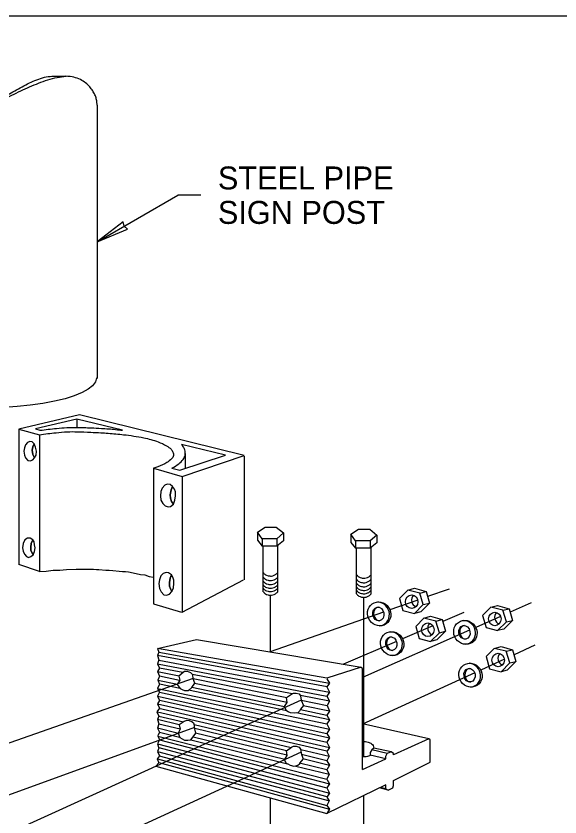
# Model space of a CAD drawing. Extents: x 99862 to 103151, y 103000 to 105076.
# Drawn here: x 102078 to 102457, y 104517 to 105076 of the extents above; entities that cross this region are included whole.
import ezdxf

# ---------------------------------------------------------------- set-up
doc = ezdxf.new("R2010")
doc.units = 0
for name, color, linetype in [('Level 1', 7, 'Continuous'), ('Level 15', 7, 'Continuous'), ('Level 2', 7, 'Continuous'), ('Level 20', 7, 'Continuous'), ('Level 3', 7, 'Continuous')]:
    doc.layers.add(name, color=color, linetype=linetype)

msp = doc.modelspace()

# ---------------------------------------------------------------- linework, layer by layer
at = {"layer": 'Level 1'}
msp.add_lwpolyline([(99862, 102999.5), (103151, 102999.5), (103151, 105075.5), (99862, 105075.5)], close=True, dxfattribs=at)
for points in [[(102194.17, 104618.02), (102191.13, 104615.31), (102191.81, 104612.61), (102190.12, 104609.56), (102192.15, 104606.86), (102193.49, 104606.18), (102195.18, 104605.51), (102197.88, 104605.51), (102200.24, 104607.53), (102202.26, 104610.58), (102201.25, 104613.62), (102200.91, 104616.33), (102199.56, 104617.68), (102197.2, 104618.69), (102195.18, 104618.69), (102194.17, 104618.02)], [(102266.33, 104600.43), (102269.71, 104602.8), (102271.05, 104603.48), (102273.08, 104603.48), (102275.1, 104603.14), (102276.11, 104601.79), (102276.45, 104598.74), (102278.14, 104595.02), (102276.11, 104592.32), (102275.44, 104590.96), (102274.09, 104589.95), (102271.73, 104589.61), (102269.03, 104589.95), (102267.34, 104590.63), (102266.33, 104591.3), (102264.98, 104594.35), (102266.67, 104597.05), (102266.33, 104600.43)], [(102194.84, 104583.86), (102191.47, 104581.5), (102192.15, 104578.45), (102190.8, 104575.75), (102191.81, 104572.7), (102193.49, 104571.69), (102195.18, 104570.68), (102197.54, 104570.68), (102199.56, 104571.01), (102201.25, 104573.04), (102202.94, 104575.75), (102202.26, 104578.79), (102201.93, 104582.17), (102200.24, 104583.53), (102198.55, 104584.2), (102196.53, 104584.54), (102194.84, 104583.86)], [(102266.33, 104563.24), (102269.71, 104565.94), (102271.05, 104566.62), (102273.08, 104566.62), (102275.1, 104565.94), (102276.11, 104564.59), (102276.79, 104560.87), (102277.8, 104557.83), (102275.44, 104554.78), (102275.44, 104554.11), (102274.09, 104553.09), (102271.73, 104552.42), (102269.03, 104553.09), (102267.34, 104554.11), (102266.33, 104554.44), (102264.98, 104557.15), (102266.67, 104560.19), (102266.33, 104563.24)]]:
    msp.add_lwpolyline(points, dxfattribs=at)
at = {"layer": 'Level 15'}
for p, q in [((102134.15, 104918.12), (102190.44, 104950.62)), ((102206.44, 104950.62), (102190.44, 104950.62)), ((102379.8, 104676.1), (102364.7, 104670.82)), ((102255.04, 104632.37), (102255.04, 104671.84)), ((102320.2, 104559.19), (102320.2, 104670.33)), ((102357.85, 104668.42), (102338.42, 104661.63)), ((102436.92, 104666.52), (102422.29, 104660.05)), ((102333.99, 104660.08), (102254.84, 104632.4)), ((102390.02, 104659.67), (102375.31, 104653.39)), ((102415.59, 104657.09), (102398.22, 104649.4)), ((102368.4, 104650.45), (102347.25, 104641.43)), ((102393.98, 104647.53), (102319.28, 104614.48)), ((102342.98, 104639.6), (102305.95, 104623.81)), ((102439.49, 104636.92), (102424.94, 104630.27)), ((102418.22, 104627.19), (102401.71, 104619.64)), ((102397.5, 104617.71), (102319.28, 104581.91)), ((102201.25, 104613.66), (101951.27, 104526.23)), ((102276.55, 104598.56), (102022.83, 104483.36)), ((102202.19, 104579.54), (101999, 104505.88)), ((102276.52, 104562.34), (102022.17, 104445.95)), ((102255.04, 104507.06), (102255.04, 104530.51)), ((102320.2, 104486.82), (102320.2, 104532.16))]:
    msp.add_line(p, q, dxfattribs=at)
msp.add_lwpolyline([(102134.15, 104918.12), (102155.41, 104926.95), (102153, 104929.01), (102152.42, 104932.12)], close=True, dxfattribs=at)
msp.add_lwpolyline([(102134.15, 104918.12), (102155.41, 104926.95), (102153, 104929.01), (102152.42, 104932.12)], close=True, dxfattribs=at)
at = {"layer": 'Level 2'}
for p, q in [((102102.68, 105033.48), (102112.32, 105033.48)), ((102079.52, 104787.43), (102079.52, 104693.2)), ((102195.73, 104770.63), (102195.73, 104760.31)), ((102094.02, 104688.35), (102079.52, 104693.2)), ((102176.3, 104618.69), (102191.51, 104615.65)), ((102194.02, 104617.89), (102177.65, 104621.06)), ((102270.32, 104603.11), (102200.63, 104616.61)), ((102176.63, 104612.61), (102190.25, 104609.79)), ((102191.71, 104612.43), (102177.65, 104615.31)), ((102201.24, 104613.7), (102266.61, 104600.63)), ((102192.19, 104606.83), (102177.65, 104609.9)), ((102266.55, 104591.16), (102198, 104605.61)), ((102200.35, 104607.7), (102264.99, 104594.33)), ((102266.67, 104597.05), (102202.08, 104610.3)), ((102296.34, 104598.07), (102275.94, 104602.02)), ((102276.49, 104598.66), (102294.66, 104595.02)), ((102296.34, 104590.96), (102277.93, 104594.74)), ((102296.34, 104584.88), (102273.01, 104589.8)), ((102275.98, 104592.05), (102294.32, 104588.26)), ((102191.5, 104581.51), (102176.3, 104585.22)), ((102177.31, 104587.58), (102194.39, 104583.54)), ((102190.87, 104575.54), (102176.3, 104579.13)), ((102177.31, 104582.17), (102192.11, 104578.6)), ((102201.97, 104581.75), (102269.51, 104565.78)), ((102266.38, 104563.28), (102202.25, 104578.9)), ((102177.65, 104576.42), (102191.74, 104572.92)), ((102265.05, 104557.26), (102201.21, 104572.99)), ((102202.88, 104576), (102266.62, 104560.61)), ((102199.47, 104571), (102267.07, 104554.2)), ((102276.18, 104564.2), (102296.01, 104559.52)), ((102294.32, 104556.47), (102276.83, 104560.73)), ((102325.76, 104563.98), (102324.67, 104562.22)), ((102324.67, 104562.22), (102324.67, 104560.27)), ((102327.29, 104565.26), (102325.76, 104563.98)), ((102277.77, 104557.92), (102296.34, 104553.43)), ((102272.9, 104552.75), (102296.01, 104547.01)), ((102294.32, 104550.05), (102275.44, 104554.7))]:
    msp.add_line(p, q, dxfattribs=at)
for points in [[(102134.15, 105013.31), (102134.15, 104822.93)], [(102133.81, 104823.27), (102133.13, 104820.57), (102131.11, 104817.86), (102128.08, 104815.49), (102123.69, 104813.13), (102118.3, 104810.76), (102111.89, 104808.73), (102104.47, 104807.04), (102096.38, 104805.35), (102087.61, 104804.34), (102078.51, 104803.32), (102069.06, 104802.65)], [(102173.6, 104760.38), (102193.49, 104754.63), (102236.66, 104769.17), (102122.01, 104797.57), (102079.52, 104787.43)], [(102152.02, 104786.75), (102119.98, 104794.53), (102091.32, 104787.77), (102094.35, 104786.75)], [(102119.98, 104794.53), (102119.98, 104788.75)], [(102079.52, 104787.43), (102094.02, 104783.71)], [(102090.31, 104777.28), (102088.96, 104778.64), (102087.27, 104778.97), (102085.59, 104778.3), (102084.24, 104776.61), (102083.56, 104774.58), (102083.23, 104772.21), (102083.56, 104769.51), (102084.24, 104767.48), (102085.92, 104765.79), (102087.61, 104765.45), (102089.3, 104766.13), (102090.64, 104767.48), (102089.3, 104769.84), (102088.96, 104772.89), (102089.3, 104775.26), (102090.31, 104777.28)], [(102094.02, 104783.71), (102094.02, 104688.35)], [(102090.64, 104767.48), (102091.66, 104769.51), (102091.99, 104772.21), (102091.32, 104774.92), (102090.31, 104777.28), (102089.3, 104775.26), (102088.96, 104772.89), (102089.3, 104769.84), (102090.64, 104767.48)], [(102186.41, 104760.38), (102191.81, 104759.02), (102223.84, 104769.51), (102193.16, 104776.95)], [(102236.66, 104768.83), (102236.66, 104682.6)], [(102173.6, 104760.38), (102173.6, 104665.7), (102193.16, 104659.95)], [(102193.49, 104754.63), (102193.49, 104659.95), (102236.32, 104682.6)], [(102186.75, 104747.53), (102185.06, 104748.88), (102183.04, 104749.22), (102181.36, 104748.54), (102179.67, 104746.51), (102178.66, 104744.15), (102178.32, 104741.1), (102178.66, 104738.06), (102180.01, 104735.69), (102181.69, 104734), (102183.72, 104733.32), (102185.4, 104733.66), (102187.43, 104735.35), (102186.08, 104737.04), (102185.4, 104739.41), (102185.06, 104741.78), (102185.74, 104745.16), (102186.75, 104747.53)], [(102187.43, 104735.35), (102188.44, 104738.06), (102188.77, 104741.1), (102188.77, 104743.81), (102188.1, 104745.84), (102186.75, 104747.53), (102185.74, 104745.16), (102185.06, 104741.78), (102185.4, 104739.41), (102186.08, 104737.04), (102187.43, 104735.35)], [(102089.3, 104710.33), (102087.61, 104711.68), (102085.59, 104711.68), (102083.9, 104710.33), (102082.55, 104707.96), (102082.21, 104704.92), (102082.55, 104702.55), (102083.56, 104700.52), (102084.91, 104698.83), (102086.26, 104698.16), (102087.95, 104698.83), (102089.63, 104699.85), (102088.62, 104701.54), (102087.95, 104703.23), (102087.95, 104705.26), (102088.28, 104707.96), (102089.3, 104710.33)], [(102089.63, 104699.85), (102090.64, 104702.22), (102090.98, 104704.92), (102090.64, 104706.95), (102090.31, 104708.98), (102089.3, 104710.33), (102088.28, 104707.96), (102087.95, 104705.26), (102087.95, 104703.23), (102088.62, 104701.54), (102089.63, 104699.85)], [(102094.02, 104688.35), (102098.74, 104688.69), (102103.46, 104689.37), (102108.18, 104689.37), (102112.9, 104689.7), (102119.65, 104690.04), (102121.67, 104690.04), (102123.69, 104690.04), (102125.72, 104690.04), (102129.76, 104690.04), (102131.78, 104690.04), (102133.81, 104689.7), (102135.49, 104689.7), (102140.22, 104689.37), (102142.58, 104689.37), (102145.27, 104689.03), (102149.66, 104688.69), (102152.02, 104688.35), (102154.04, 104688.35), (102156.06, 104688.01), (102161.46, 104687), (102164.49, 104686.32), (102167.53, 104685.98), (102170.56, 104684.97), (102173.6, 104684.29)], [(102186.08, 104685.98), (102184.05, 104687.34), (102182.37, 104687.67), (102180.34, 104687), (102178.66, 104685.31), (102177.65, 104682.6), (102177.31, 104679.9), (102177.65, 104676.52), (102178.99, 104674.15), (102180.68, 104672.12), (102182.7, 104671.78), (102184.73, 104672.46), (102186.41, 104674.49), (102185.4, 104676.18), (102184.73, 104678.21), (102184.73, 104680.57), (102185.06, 104683.62), (102186.08, 104685.98)], [(102186.41, 104674.49), (102187.43, 104676.85), (102187.76, 104679.9), (102187.76, 104682.26), (102187.09, 104684.29), (102186.08, 104685.98), (102185.06, 104683.62), (102184.73, 104680.57), (102184.73, 104678.21), (102185.4, 104676.18), (102186.41, 104674.49)], [(102176.3, 104634.59), (102203.61, 104641.01), (102318.26, 104621.74), (102294.32, 104613.96)], [(102176.3, 104634.59), (102177.31, 104632.22), (102176.3, 104629.85), (102177.31, 104626.81), (102176.3, 104624.1), (102177.65, 104621.06), (102176.3, 104618.69), (102177.65, 104615.31), (102176.63, 104612.61), (102177.65, 104609.9), (102176.3, 104606.86), (102177.65, 104604.15), (102176.3, 104601.45), (102177.65, 104598.4), (102176.3, 104596.04), (102177.65, 104592.99), (102175.96, 104590.63), (102177.31, 104587.58), (102176.3, 104585.22), (102177.31, 104582.17), (102176.3, 104579.13), (102177.65, 104576.42), (102176.63, 104573.72), (102177.65, 104571.01), (102176.3, 104568.31), (102177.31, 104565.27), (102176.3, 104562.9), (102177.65, 104559.86), (102176.39, 104557.96)], [(102294.32, 104613.96), (102176.3, 104634.59)], [(102294.66, 104607.87), (102176.3, 104629.85)], [(102177.31, 104632.22), (102296.34, 104610.58)], [(102176.3, 104624.1), (102294.32, 104601.45)], [(102177.31, 104626.47), (102296.34, 104604.15)], [(102319.28, 104550.39), (102319.28, 104620.72), (102317.93, 104621.74)], [(102294.32, 104613.62), (102296.34, 104610.58), (102294.32, 104607.87), (102296.34, 104604.15), (102294.32, 104601.45), (102296.34, 104598.07), (102294.66, 104595.02), (102296.34, 104590.96), (102294.32, 104588.26), (102296.34, 104584.88), (102294.32, 104582.17), (102296.34, 104578.45), (102294.32, 104575.41), (102296.34, 104572.37), (102294.32, 104569.32), (102296.34, 104565.6), (102294.32, 104562.9), (102296.01, 104559.52), (102294.32, 104556.47), (102296.34, 104553.43), (102294.32, 104550.05), (102296.01, 104547.01), (102294.32, 104543.62), (102296.34, 104540.24), (102294.32, 104537.54), (102296.34, 104533.82), (102294.32, 104531.11), (102296.01, 104528.41), (102294.32, 104525.36), (102296.34, 104522.66), (102294.32, 104519.62)], [(102176.3, 104606.86), (102294.32, 104582.17)], [(102176.3, 104601.45), (102294.32, 104575.41)], [(102177.65, 104604.15), (102296.34, 104578.45)], [(102176.3, 104596.04), (102294.32, 104569.32)], [(102177.65, 104598.74), (102296.34, 104572.37)], [(102176.3, 104590.63), (102294.32, 104563.24)], [(102177.31, 104592.99), (102296.34, 104565.6)], [(102365.47, 104571.69), (102319.28, 104582.17)], [(102176.67, 104573.62), (102294.32, 104543.62)], [(102366.49, 104555.46), (102366.49, 104571.01), (102365.47, 104571.69), (102340.86, 104560.53)], [(102176.3, 104568.31), (102294.32, 104537.54)], [(102177.61, 104570.94), (102296.34, 104540.24)], [(102176.3, 104562.9), (102294.32, 104531.45)], [(102177.19, 104565.64), (102296.34, 104533.82)], [(102319.28, 104550.39), (102335.46, 104557.83), (102335.46, 104559.52), (102336.47, 104561.55)], [(102336.47, 104561.55), (102325.76, 104563.98)], [(102339.17, 104562.56), (102327.29, 104565.26)], [(102340.86, 104560.53), (102340.86, 104561.55), (102339.17, 104562.56), (102336.47, 104561.55)], [(102176.39, 104557.96), (102176.17, 104557.73), (102177.28, 104555.08), (102175.13, 104552.65)], [(102176.27, 104557.83), (102294.32, 104525.36)], [(102177.25, 104555.14), (102296.34, 104522.66)], [(102177.6, 104559.78), (102296.34, 104528.41)], [(102335.46, 104557.83), (102324.67, 104560.27)], [(102335.46, 104536.86), (102337.15, 104535.85), (102340.52, 104537.54), (102340.86, 104539.23), (102340.86, 104542.61), (102366.49, 104555.46)], [(102175.15, 104552.68), (102294.32, 104519.62)], [(102335.46, 104536.86), (102335.46, 104539.57), (102294.32, 104519.62)], [(102337.15, 104535.85), (102331.2, 104537.5)], [(102335.46, 104536.86), (102331.92, 104537.85)]]:
    msp.add_lwpolyline(points, dxfattribs=at)
for points in [[(102007.57, 105033.5), (102005.16, 105033.34), (102001.46, 105032.85), (101996.88, 105031.09), (101993.27, 105028.76), (101990.45, 105026.13), (101988.4, 105023.3), (101986.84, 105020.48), (101985.87, 105017.46), (101985.38, 105014.44), (101985.38, 105011.51), (101985.97, 105008.59), (101987.04, 105005.77), (101988.79, 105003.14), (101991.23, 105000.7), (101994.54, 104998.56), (101998.83, 104997), (102003.99, 104996.12), (102010.13, 104996.12), (102016.85, 104996.9), (102023.67, 104998.46), (102030.49, 105000.6), (102037.21, 105003.04), (102043.74, 105005.67), (102050.16, 105008.49), (102056.4, 105011.42), (102059.56, 105013.41), (102068.77, 105017.46), (102074.81, 105020.38), (102080.95, 105023.3), (102087.18, 105026.13), (102093.42, 105028.76), (102099.75, 105031.09), (102106.28, 105032.85), (102110.56, 105033.34), (102112.71, 105033.47)], [(102060, 105013.48), (102060.6, 105013.82), (102062.93, 105015.22), (102066.93, 105017.5), (102071.8, 105020.52), (102076.77, 105023.44), (102081.83, 105026.27), (102086.99, 105028.9), (102092.16, 105031.14), (102097.42, 105032.99), (102100.93, 105033.48), (102102.68, 105033.48)], [(102134.15, 105013.31), (102134.15, 105013.7), (102134.15, 105015.16), (102133.76, 105017.6), (102132.78, 105020.52), (102131.22, 105023.44), (102129.18, 105026.27), (102126.35, 105028.9), (102122.75, 105031.24), (102118.17, 105032.99), (102114.47, 105033.48), (102112.32, 105033.48)]]:
    msp.add_open_spline(points, degree=3, dxfattribs=at)
for points in [[(102094.02, 104783.71), (102105.57, 104785.08), (102113.38, 104785.75), (102120.32, 104785.76), (102129.76, 104785.4), (102136.84, 104785.06), (102141.9, 104784.72), (102152.69, 104783.71), (102166.69, 104781.51), (102176.77, 104778.72), (102182.7, 104775.93), (102185.74, 104773.56), (102187.09, 104771.54), (102187.43, 104769.17), (102186.08, 104766.8), (102182.83, 104764.34), (102176.58, 104761.33), (102173.6, 104760.38)], [(102094.35, 104786.75), (102105.9, 104788.12), (102113.12, 104788.63), (102119.98, 104788.75), (102130.1, 104788.44), (102137.18, 104788.1), (102142.24, 104787.77), (102152.02, 104786.75)], [(102186.41, 104760.38), (102191.13, 104763.42), (102194.17, 104766.46), (102195.52, 104769.17), (102195.69, 104771.54), (102195.35, 104773.06), (102194.17, 104775.42), (102193.16, 104776.95)], [(102319.28, 104570), (102323.26, 104569.48), (102325.53, 104568.25), (102326.69, 104566.96), (102327.29, 104565.26)], [(102324.67, 104560.19), (102323.47, 104559.56), (102321.87, 104559.19), (102320.34, 104559.19), (102319.28, 104559.18)]]:
    msp.add_spline(points, degree=3, dxfattribs=at)
at = {"layer": 'Level 3'}
for p, q in [((102359.29, 104673.35), (102363.67, 104674.37)), ((102361.65, 104665.24), (102366.03, 104666.25)), ((102417.22, 104661.38), (102421.61, 104662.39)), ((102370.51, 104653.8), (102374.89, 104654.82)), ((102419.58, 104653.26), (102423.97, 104654.28)), ((102372.87, 104645.69), (102377.25, 104646.7)), ((102419.55, 104632.71), (102423.94, 104633.73)), ((102421.92, 104624.6), (102426.3, 104625.61))]:
    msp.add_line(p, q, dxfattribs=at)
for points in [[(102259.45, 104711.13), (102249.33, 104711.13), (102245.96, 104715.86), (102251.35, 104719.25), (102259.11, 104719.25), (102264.17, 104715.19), (102259.45, 104711.13)], [(102324.61, 104709.62), (102314.49, 104709.62), (102311.12, 104714.36), (102316.52, 104717.74), (102324.27, 104717.74), (102329.33, 104713.68), (102324.61, 104709.62)], [(102245.96, 104715.86), (102245.96, 104710.12), (102249.33, 104706.06)], [(102264.17, 104715.19), (102264.17, 104709.78), (102259.45, 104706.06)], [(102311.12, 104714.36), (102311.12, 104708.61), (102314.49, 104704.55)], [(102329.33, 104713.68), (102329.33, 104708.27), (102324.61, 104704.55)], [(102249.33, 104711.13), (102249.33, 104706.06)], [(102259.45, 104711.13), (102259.45, 104706.06), (102249.33, 104706.06)], [(102250.01, 104674.27), (102250.01, 104706.06)], [(102260.12, 104674.27), (102260.12, 104706.4)], [(102314.49, 104709.62), (102314.49, 104704.55)], [(102324.61, 104709.62), (102324.61, 104704.55), (102314.49, 104704.55)], [(102315.17, 104672.77), (102315.17, 104704.55)], [(102325.28, 104672.77), (102325.28, 104704.89)], [(102350.86, 104675.38), (102355.58, 104676.73), (102363.67, 104674.37), (102366.03, 104666.25), (102359.96, 104660.16), (102355.58, 104659.15)], [(102408.79, 104663.41), (102413.51, 104664.76), (102421.61, 104662.39), (102423.97, 104654.28), (102417.9, 104648.19), (102413.51, 104647.18)], [(102362.08, 104655.83), (102366.8, 104657.18), (102374.89, 104654.82), (102377.25, 104646.7), (102371.18, 104640.62), (102366.8, 104639.6)], [(102411.12, 104634.74), (102415.85, 104636.09), (102423.94, 104633.73), (102426.3, 104625.61), (102420.23, 104619.53), (102415.85, 104618.51)]]:
    msp.add_lwpolyline(points, dxfattribs=at)
for points in [[(102350.86, 104675.38), (102345.12, 104669.63), (102347.48, 104661.18), (102355.58, 104659.15), (102361.65, 104665.24), (102359.29, 104673.35)], [(102408.79, 104663.41), (102403.06, 104657.66), (102405.42, 104649.21), (102413.51, 104647.18), (102419.58, 104653.26), (102417.22, 104661.38)], [(102362.08, 104655.83), (102356.35, 104650.08), (102358.71, 104641.63), (102366.8, 104639.6), (102372.87, 104645.69), (102370.51, 104653.8)], [(102411.12, 104634.74), (102405.39, 104628.99), (102407.75, 104620.54), (102415.85, 104618.51), (102421.92, 104624.6), (102419.55, 104632.71)]]:
    msp.add_lwpolyline(points, close=True, dxfattribs=at)
for centre, major_axis, ratio in [((102330.92, 104658.78), (-4.86, 6.97), 0.941303), ((102353.59, 104667.27), (0, -4.73), 0.926005), ((102330.28, 104658.78), (-0.84, 4.73), 0.813195), ((102391, 104645.93), (-4.86, 6.97), 0.941303), ((102411.53, 104655.29), (0, -4.73), 0.926005), ((102364.82, 104647.72), (0, -4.73), 0.926005), ((102390.37, 104645.93), (-0.84, 4.73), 0.813195), ((102339.99, 104638.05), (-4.86, 6.97), 0.941303), ((102339.35, 104638.05), (-0.84, 4.73), 0.813195), ((102413.86, 104626.63), (0, -4.73), 0.926005), ((102394.55, 104616.06), (-4.86, 6.97), 0.941303), ((102393.91, 104616.06), (-0.84, 4.73), 0.813195)]:
    msp.add_ellipse(centre, major_axis=major_axis, ratio=ratio, dxfattribs=at)
for centre, major_axis, ratio, start_param, end_param in [((102329.86, 104658.78), (-4.86, 6.97), 0.941303, 2.626025, 5.636995), ((102357.86, 104668.34), (0, -4.73), 0.926005, 3.893934, 5.988329), ((102330.92, 104658.78), (-0.84, 4.73), 0.813195, 6.220736, 9.199602), ((102415.8, 104656.37), (0, -4.73), 0.926005, 3.893934, 5.988329), ((102369.09, 104648.79), (0, -4.73), 0.926005, 3.893934, 5.988329), ((102391, 104645.93), (-0.84, 4.73), 0.813195, 6.220736, 9.199602), ((102389.94, 104645.93), (-4.86, 6.97), 0.941303, 2.626025, 5.636995), ((102338.92, 104638.05), (-4.86, 6.97), 0.941303, 2.626025, 5.636995), ((102339.99, 104638.05), (-0.84, 4.73), 0.813195, 6.220736, 9.199602), ((102418.13, 104627.7), (0, -4.73), 0.926005, 3.893934, 5.988329), ((102393.49, 104616.06), (-4.86, 6.97), 0.941303, 2.626025, 5.636995), ((102394.55, 104616.06), (-0.84, 4.73), 0.813195, 6.220736, 9.199602)]:
    msp.add_ellipse(centre, major_axis=major_axis, ratio=ratio, start_param=start_param, end_param=end_param, dxfattribs=at)
for points in [[(102250.01, 104687.61), (102251.54, 104686.09), (102253.38, 104685.41), (102255.7, 104685.2), (102257.59, 104685.75), (102259.31, 104686.74), (102260.12, 104687.61)], [(102250.01, 104684.43), (102251.54, 104682.9), (102253.38, 104682.23), (102255.7, 104682.02), (102257.59, 104682.57), (102259.31, 104683.56), (102260.12, 104684.43)], [(102315.17, 104686.11), (102316.7, 104684.58), (102318.54, 104683.91), (102320.86, 104683.7), (102322.75, 104684.25), (102324.47, 104685.24), (102325.28, 104686.11)], [(102250.01, 104681.67), (102251.54, 104680.14), (102253.38, 104679.47), (102255.7, 104679.25), (102257.59, 104679.81), (102259.31, 104680.8), (102260.12, 104681.67)], [(102250.01, 104679.05), (102251.54, 104677.52), (102253.38, 104676.85), (102255.7, 104676.64), (102257.59, 104677.19), (102259.31, 104678.18), (102260.12, 104679.05)], [(102315.17, 104682.93), (102316.7, 104681.4), (102318.54, 104680.73), (102320.86, 104680.52), (102322.75, 104681.07), (102324.47, 104682.06), (102325.28, 104682.93)], [(102315.17, 104680.16), (102316.7, 104678.63), (102318.54, 104677.96), (102320.86, 104677.75), (102322.75, 104678.3), (102324.47, 104679.29), (102325.28, 104680.16)], [(102250.01, 104676.73), (102251.54, 104675.21), (102253.38, 104674.54), (102255.7, 104674.32), (102257.59, 104674.88), (102259.31, 104675.87), (102260.12, 104676.73)], [(102250.01, 104674.27), (102251.54, 104672.75), (102253.38, 104672.07), (102255.7, 104671.86), (102257.59, 104672.41), (102259.31, 104673.4), (102260.12, 104674.27)], [(102315.17, 104677.54), (102316.7, 104676.02), (102318.54, 104675.35), (102320.86, 104675.13), (102322.75, 104675.68), (102324.47, 104676.68), (102325.28, 104677.54)], [(102315.17, 104675.23), (102316.7, 104673.7), (102318.54, 104673.03), (102320.86, 104672.82), (102322.75, 104673.37), (102324.47, 104674.36), (102325.28, 104675.23)], [(102315.17, 104672.77), (102316.7, 104671.24), (102318.54, 104670.57), (102320.86, 104670.36), (102322.75, 104670.91), (102324.47, 104671.9), (102325.28, 104672.77)]]:
    msp.add_spline(points, degree=3, dxfattribs=at)

# ---------------------------------------------------------------- texts
at = {"layer": 'Level 20'}
for s, p in [('STEEL PIPE', (102218.43, 104954.62)), ('SIGN POST', (102218.43, 104930.62))]:
    msp.add_text(s, height=16, rotation=360, dxfattribs=at).set_placement(p)

doc.saveas('drawing.dxf')
